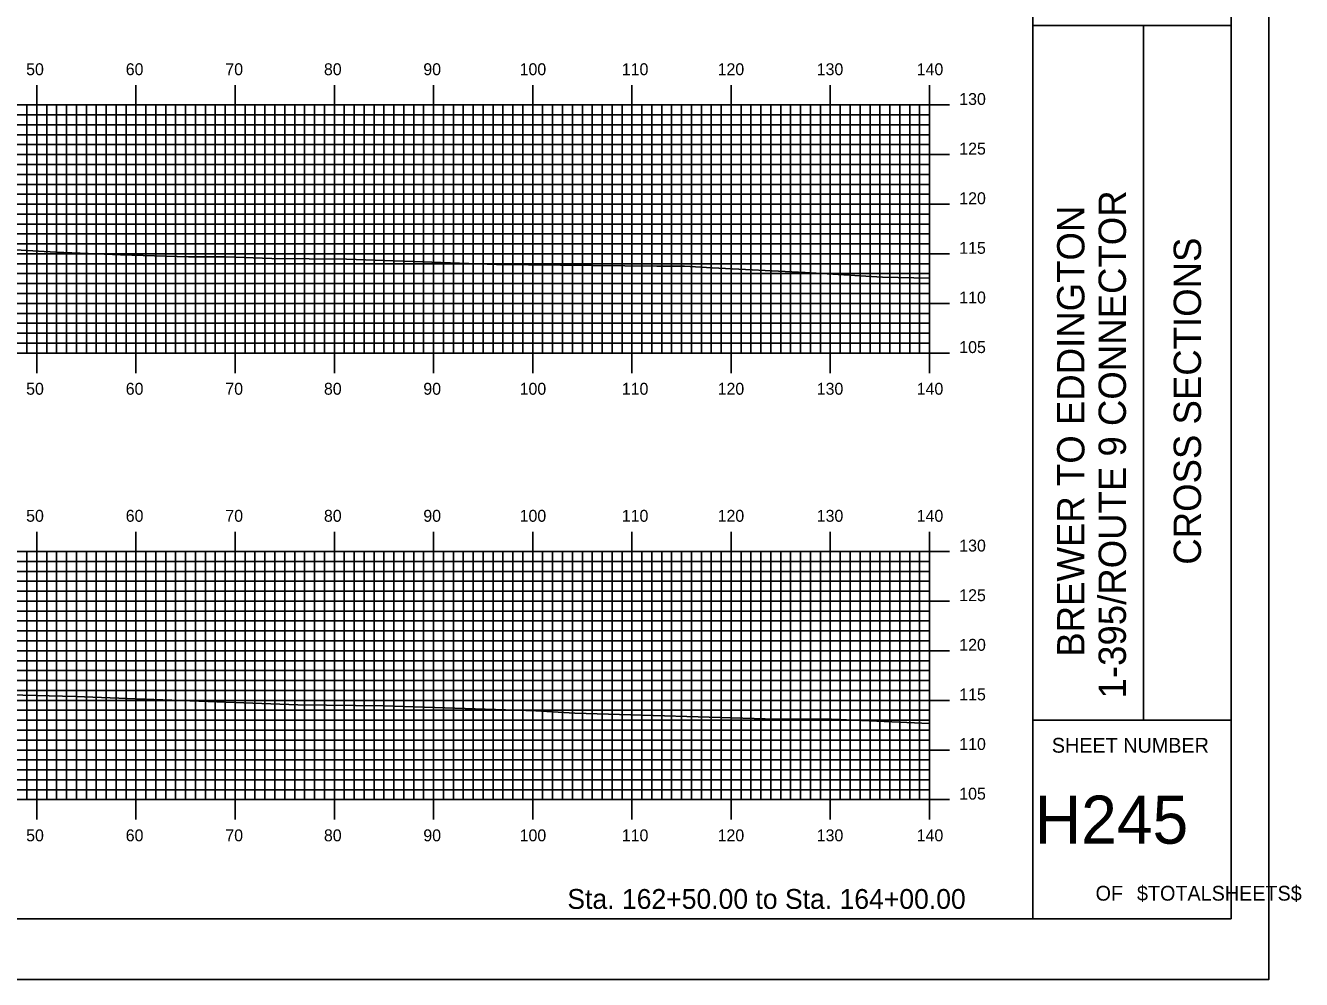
# Model space of a CAD drawing. Extents: x 1780680 to 1781023, y 442591 to 442811.
# Drawn here: x 1780894.2 to 1781022.9, y 442590.5 to 442686.7 of the extents above; entities that cross this region are included whole.
import ezdxf

# ---------------------------------------------------------------- set-up
doc = ezdxf.new("R2010")
doc.units = 0
for name, color, linetype in [('BORDER', 7, 'Continuous'), ('H_V ANNOTATION', 7, 'Continuous'), ('MAJOR', 7, 'Continuous'), ('MINOR', 7, 'Continuous'), ('PLOT BOUNDARY', 7, 'Continuous'), ('S_Roadway_Centerline', 7, 'Continuous')]:
    doc.layers.add(name, color=color, linetype=linetype)

msp = doc.modelspace()

# ---------------------------------------------------------------- linework, layer by layer
at = {"layer": 'BORDER'}
for p, q in [((1780995.78, 442596.67), (1780995.78, 442806.67)), ((1780995.78, 442686.67), (1781015.78, 442686.67)), ((1781006.96, 442616.67), (1781006.96, 442686.67)), ((1780995.78, 442616.67), (1781015.78, 442616.67))]:
    msp.add_line(p, q, dxfattribs=at)
msp.add_lwpolyline([(1780695.78, 442596.67), (1781015.78, 442596.67), (1781015.78, 442806.67), (1780695.78, 442806.67)], close=True, dxfattribs=at)
at = {"layer": 'MAJOR'}
for p, q in [((1780895.38, 442680.67), (1780895.38, 442678.67)), ((1780905.38, 442680.67), (1780905.38, 442678.67)), ((1780915.38, 442680.67), (1780915.38, 442678.67)), ((1780925.38, 442680.67), (1780925.38, 442678.67)), ((1780935.38, 442680.67), (1780935.38, 442678.67)), ((1780945.38, 442680.67), (1780945.38, 442678.67)), ((1780955.38, 442680.67), (1780955.38, 442678.67)), ((1780965.38, 442680.67), (1780965.38, 442678.67)), ((1780975.38, 442680.67), (1780975.38, 442678.67)), ((1780985.38, 442680.67), (1780985.38, 442678.67)), ((1780705.38, 442678.67), (1780985.38, 442678.67)), ((1780705.38, 442678.67), (1780985.38, 442678.67)), ((1780895.38, 442653.67), (1780895.38, 442678.67)), ((1780905.38, 442653.67), (1780905.38, 442678.67)), ((1780915.38, 442653.67), (1780915.38, 442678.67)), ((1780925.38, 442653.67), (1780925.38, 442678.67)), ((1780935.38, 442653.67), (1780935.38, 442678.67)), ((1780945.38, 442653.67), (1780945.38, 442678.67)), ((1780955.38, 442653.67), (1780955.38, 442678.67)), ((1780965.38, 442653.67), (1780965.38, 442678.67)), ((1780975.38, 442653.67), (1780975.38, 442678.67)), ((1780987.39, 442678.67), (1780983.38, 442678.67)), ((1780985.38, 442653.67), (1780985.38, 442678.67)), ((1780985.38, 442653.67), (1780985.38, 442678.67)), ((1780705.38, 442673.67), (1780985.38, 442673.67)), ((1780987.39, 442673.67), (1780983.38, 442673.67)), ((1780705.38, 442668.67), (1780985.38, 442668.67)), ((1780987.39, 442668.67), (1780983.38, 442668.67)), ((1780705.38, 442663.67), (1780985.38, 442663.67)), ((1780987.39, 442663.67), (1780983.38, 442663.67)), ((1780705.38, 442658.67), (1780985.38, 442658.67)), ((1780987.39, 442658.67), (1780983.38, 442658.67)), ((1780705.38, 442653.67), (1780985.38, 442653.67)), ((1780705.38, 442653.67), (1780985.38, 442653.67)), ((1780895.38, 442651.66), (1780895.38, 442653.67)), ((1780905.38, 442651.66), (1780905.38, 442653.67)), ((1780915.38, 442651.66), (1780915.38, 442653.67)), ((1780925.38, 442651.66), (1780925.38, 442653.67)), ((1780935.38, 442651.66), (1780935.38, 442653.67)), ((1780945.38, 442651.66), (1780945.38, 442653.67)), ((1780955.38, 442651.66), (1780955.38, 442653.67)), ((1780965.38, 442651.66), (1780965.38, 442653.67)), ((1780975.38, 442651.66), (1780975.38, 442653.67)), ((1780987.39, 442653.67), (1780983.38, 442653.67)), ((1780985.38, 442651.66), (1780985.38, 442653.67)), ((1780895.38, 442635.67), (1780895.38, 442633.67)), ((1780905.38, 442635.67), (1780905.38, 442633.67)), ((1780915.38, 442635.67), (1780915.38, 442633.67)), ((1780925.38, 442635.67), (1780925.38, 442633.67)), ((1780935.38, 442635.67), (1780935.38, 442633.67)), ((1780945.38, 442635.67), (1780945.38, 442633.67)), ((1780955.38, 442635.67), (1780955.38, 442633.67)), ((1780965.38, 442635.67), (1780965.38, 442633.67)), ((1780975.38, 442635.67), (1780975.38, 442633.67)), ((1780985.38, 442635.67), (1780985.38, 442633.67)), ((1780705.38, 442633.67), (1780985.38, 442633.67)), ((1780705.38, 442633.67), (1780985.38, 442633.67)), ((1780895.38, 442608.67), (1780895.38, 442633.67)), ((1780905.38, 442608.67), (1780905.38, 442633.67)), ((1780915.38, 442608.67), (1780915.38, 442633.67)), ((1780925.38, 442608.67), (1780925.38, 442633.67)), ((1780935.38, 442608.67), (1780935.38, 442633.67)), ((1780945.38, 442608.67), (1780945.38, 442633.67)), ((1780955.38, 442608.67), (1780955.38, 442633.67)), ((1780965.38, 442608.67), (1780965.38, 442633.67)), ((1780975.38, 442608.67), (1780975.38, 442633.67)), ((1780987.39, 442633.67), (1780983.38, 442633.67)), ((1780985.38, 442608.67), (1780985.38, 442633.67)), ((1780985.38, 442608.67), (1780985.38, 442633.67)), ((1780705.38, 442628.67), (1780985.38, 442628.67)), ((1780987.39, 442628.67), (1780983.38, 442628.67)), ((1780705.38, 442623.67), (1780985.38, 442623.67)), ((1780987.39, 442623.67), (1780983.38, 442623.67)), ((1780705.38, 442618.67), (1780985.38, 442618.67)), ((1780987.39, 442618.67), (1780983.38, 442618.67)), ((1780705.38, 442613.67), (1780985.38, 442613.67)), ((1780987.39, 442613.67), (1780983.38, 442613.67)), ((1780705.38, 442608.67), (1780985.38, 442608.67)), ((1780705.38, 442608.67), (1780985.38, 442608.67)), ((1780895.38, 442606.66), (1780895.38, 442608.67)), ((1780905.38, 442606.66), (1780905.38, 442608.67)), ((1780915.38, 442606.66), (1780915.38, 442608.67)), ((1780925.38, 442606.66), (1780925.38, 442608.67)), ((1780935.38, 442606.66), (1780935.38, 442608.67)), ((1780945.38, 442606.66), (1780945.38, 442608.67)), ((1780955.38, 442606.66), (1780955.38, 442608.67)), ((1780965.38, 442606.66), (1780965.38, 442608.67)), ((1780975.38, 442606.66), (1780975.38, 442608.67)), ((1780987.39, 442608.67), (1780983.38, 442608.67)), ((1780985.38, 442606.66), (1780985.38, 442608.67))]:
    msp.add_line(p, q, dxfattribs=at)
at = {"layer": 'MINOR'}
for p, q in [((1780894.38, 442653.67), (1780894.38, 442678.67)), ((1780896.38, 442653.67), (1780896.38, 442678.67)), ((1780897.38, 442653.67), (1780897.38, 442678.67)), ((1780898.38, 442653.67), (1780898.38, 442678.67)), ((1780899.38, 442653.67), (1780899.38, 442678.67)), ((1780900.38, 442653.67), (1780900.38, 442678.67)), ((1780901.38, 442653.67), (1780901.38, 442678.67)), ((1780902.38, 442653.67), (1780902.38, 442678.67)), ((1780903.38, 442653.67), (1780903.38, 442678.67)), ((1780904.38, 442653.67), (1780904.38, 442678.67)), ((1780906.38, 442653.67), (1780906.38, 442678.67)), ((1780907.38, 442653.67), (1780907.38, 442678.67)), ((1780908.38, 442653.67), (1780908.38, 442678.67)), ((1780909.38, 442653.67), (1780909.38, 442678.67)), ((1780910.38, 442653.67), (1780910.38, 442678.67)), ((1780911.38, 442653.67), (1780911.38, 442678.67)), ((1780912.38, 442653.67), (1780912.38, 442678.67)), ((1780913.38, 442653.67), (1780913.38, 442678.67)), ((1780914.38, 442653.67), (1780914.38, 442678.67)), ((1780916.38, 442653.67), (1780916.38, 442678.67)), ((1780917.38, 442653.67), (1780917.38, 442678.67)), ((1780918.38, 442653.67), (1780918.38, 442678.67)), ((1780919.38, 442653.67), (1780919.38, 442678.67)), ((1780920.38, 442653.67), (1780920.38, 442678.67)), ((1780921.38, 442653.67), (1780921.38, 442678.67)), ((1780922.38, 442653.67), (1780922.38, 442678.67)), ((1780923.38, 442653.67), (1780923.38, 442678.67)), ((1780924.38, 442653.67), (1780924.38, 442678.67)), ((1780926.38, 442653.67), (1780926.38, 442678.67)), ((1780927.38, 442653.67), (1780927.38, 442678.67)), ((1780928.38, 442653.67), (1780928.38, 442678.67)), ((1780929.38, 442653.67), (1780929.38, 442678.67)), ((1780930.38, 442653.67), (1780930.38, 442678.67)), ((1780931.38, 442653.67), (1780931.38, 442678.67)), ((1780932.38, 442653.67), (1780932.38, 442678.67)), ((1780933.38, 442653.67), (1780933.38, 442678.67)), ((1780934.38, 442653.67), (1780934.38, 442678.67)), ((1780936.38, 442653.67), (1780936.38, 442678.67)), ((1780937.38, 442653.67), (1780937.38, 442678.67)), ((1780938.38, 442653.67), (1780938.38, 442678.67)), ((1780939.38, 442653.67), (1780939.38, 442678.67)), ((1780940.38, 442653.67), (1780940.38, 442678.67)), ((1780941.38, 442653.67), (1780941.38, 442678.67)), ((1780942.38, 442653.67), (1780942.38, 442678.67)), ((1780943.38, 442653.67), (1780943.38, 442678.67)), ((1780944.38, 442653.67), (1780944.38, 442678.67)), ((1780946.38, 442653.67), (1780946.38, 442678.67)), ((1780947.38, 442653.67), (1780947.38, 442678.67)), ((1780948.38, 442653.67), (1780948.38, 442678.67)), ((1780949.38, 442653.67), (1780949.38, 442678.67)), ((1780950.38, 442653.67), (1780950.38, 442678.67)), ((1780951.38, 442653.67), (1780951.38, 442678.67)), ((1780952.38, 442653.67), (1780952.38, 442678.67)), ((1780953.38, 442653.67), (1780953.38, 442678.67)), ((1780954.38, 442653.67), (1780954.38, 442678.67)), ((1780956.38, 442653.67), (1780956.38, 442678.67)), ((1780957.38, 442653.67), (1780957.38, 442678.67)), ((1780958.38, 442653.67), (1780958.38, 442678.67)), ((1780959.38, 442653.67), (1780959.38, 442678.67)), ((1780960.38, 442653.67), (1780960.38, 442678.67)), ((1780961.38, 442653.67), (1780961.38, 442678.67)), ((1780962.38, 442653.67), (1780962.38, 442678.67)), ((1780963.38, 442653.67), (1780963.38, 442678.67)), ((1780964.38, 442653.67), (1780964.38, 442678.67)), ((1780966.38, 442653.67), (1780966.38, 442678.67)), ((1780967.38, 442653.67), (1780967.38, 442678.67)), ((1780968.38, 442653.67), (1780968.38, 442678.67)), ((1780969.38, 442653.67), (1780969.38, 442678.67)), ((1780970.38, 442653.67), (1780970.38, 442678.67)), ((1780971.38, 442653.67), (1780971.38, 442678.67)), ((1780972.38, 442653.67), (1780972.38, 442678.67)), ((1780973.38, 442653.67), (1780973.38, 442678.67)), ((1780974.38, 442653.67), (1780974.38, 442678.67)), ((1780976.38, 442653.67), (1780976.38, 442678.67)), ((1780977.38, 442653.67), (1780977.38, 442678.67)), ((1780978.38, 442653.67), (1780978.38, 442678.67)), ((1780979.38, 442653.67), (1780979.38, 442678.67)), ((1780980.38, 442653.67), (1780980.38, 442678.67)), ((1780981.38, 442653.67), (1780981.38, 442678.67)), ((1780982.38, 442653.67), (1780982.38, 442678.67)), ((1780983.38, 442653.67), (1780983.38, 442678.67)), ((1780984.38, 442653.67), (1780984.38, 442678.67)), ((1780705.38, 442677.67), (1780985.38, 442677.67)), ((1780985.38, 442677.67), (1780983.38, 442677.67)), ((1780705.38, 442676.67), (1780985.38, 442676.67)), ((1780705.38, 442675.67), (1780985.38, 442675.67)), ((1780985.38, 442676.67), (1780983.38, 442676.67)), ((1780985.38, 442675.67), (1780983.38, 442675.67)), ((1780705.38, 442674.67), (1780985.38, 442674.67)), ((1780985.38, 442674.67), (1780983.38, 442674.67)), ((1780705.38, 442672.67), (1780985.38, 442672.67)), ((1780705.38, 442671.67), (1780985.38, 442671.67)), ((1780985.38, 442672.67), (1780983.38, 442672.67)), ((1780985.38, 442671.67), (1780983.38, 442671.67)), ((1780705.38, 442670.67), (1780985.38, 442670.67)), ((1780985.38, 442670.67), (1780983.38, 442670.67)), ((1780705.38, 442669.67), (1780985.38, 442669.67)), ((1780985.38, 442669.67), (1780983.38, 442669.67)), ((1780705.38, 442667.67), (1780985.38, 442667.67)), ((1780705.38, 442666.67), (1780985.38, 442666.67)), ((1780985.38, 442667.67), (1780983.38, 442667.67)), ((1780985.38, 442666.67), (1780983.38, 442666.67)), ((1780705.38, 442665.67), (1780985.38, 442665.67)), ((1780985.38, 442665.67), (1780983.38, 442665.67)), ((1780705.38, 442664.67), (1780985.38, 442664.67)), ((1780985.38, 442664.67), (1780983.38, 442664.67)), ((1780705.38, 442662.67), (1780985.38, 442662.67)), ((1780985.38, 442662.67), (1780983.38, 442662.67)), ((1780705.38, 442661.67), (1780985.38, 442661.67)), ((1780985.38, 442661.67), (1780983.38, 442661.67)), ((1780705.38, 442660.67), (1780985.38, 442660.67)), ((1780985.38, 442660.67), (1780983.38, 442660.67)), ((1780705.38, 442659.67), (1780985.38, 442659.67)), ((1780985.38, 442659.67), (1780983.38, 442659.67)), ((1780705.38, 442657.67), (1780985.38, 442657.67)), ((1780985.38, 442657.67), (1780983.38, 442657.67)), ((1780705.38, 442656.67), (1780985.38, 442656.67)), ((1780985.38, 442656.67), (1780983.38, 442656.67)), ((1780705.38, 442655.67), (1780985.38, 442655.67)), ((1780985.38, 442655.67), (1780983.38, 442655.67)), ((1780705.38, 442654.67), (1780985.38, 442654.67)), ((1780985.38, 442654.67), (1780983.38, 442654.67)), ((1780894.38, 442608.67), (1780894.38, 442633.67)), ((1780896.38, 442608.67), (1780896.38, 442633.67)), ((1780897.38, 442608.67), (1780897.38, 442633.67)), ((1780898.38, 442608.67), (1780898.38, 442633.67)), ((1780899.38, 442608.67), (1780899.38, 442633.67)), ((1780900.38, 442608.67), (1780900.38, 442633.67)), ((1780901.38, 442608.67), (1780901.38, 442633.67)), ((1780902.38, 442608.67), (1780902.38, 442633.67)), ((1780903.38, 442608.67), (1780903.38, 442633.67)), ((1780904.38, 442608.67), (1780904.38, 442633.67)), ((1780906.38, 442608.67), (1780906.38, 442633.67)), ((1780907.38, 442608.67), (1780907.38, 442633.67)), ((1780908.38, 442608.67), (1780908.38, 442633.67)), ((1780909.38, 442608.67), (1780909.38, 442633.67)), ((1780910.38, 442608.67), (1780910.38, 442633.67)), ((1780911.38, 442608.67), (1780911.38, 442633.67)), ((1780912.38, 442608.67), (1780912.38, 442633.67)), ((1780913.38, 442608.67), (1780913.38, 442633.67)), ((1780914.38, 442608.67), (1780914.38, 442633.67)), ((1780916.38, 442608.67), (1780916.38, 442633.67)), ((1780917.38, 442608.67), (1780917.38, 442633.67)), ((1780918.38, 442608.67), (1780918.38, 442633.67)), ((1780919.38, 442608.67), (1780919.38, 442633.67)), ((1780920.38, 442608.67), (1780920.38, 442633.67)), ((1780921.38, 442608.67), (1780921.38, 442633.67)), ((1780922.38, 442608.67), (1780922.38, 442633.67)), ((1780923.38, 442608.67), (1780923.38, 442633.67)), ((1780924.38, 442608.67), (1780924.38, 442633.67)), ((1780926.38, 442608.67), (1780926.38, 442633.67)), ((1780927.38, 442608.67), (1780927.38, 442633.67)), ((1780928.38, 442608.67), (1780928.38, 442633.67)), ((1780929.38, 442608.67), (1780929.38, 442633.67)), ((1780930.38, 442608.67), (1780930.38, 442633.67)), ((1780931.38, 442608.67), (1780931.38, 442633.67)), ((1780932.38, 442608.67), (1780932.38, 442633.67)), ((1780933.38, 442608.67), (1780933.38, 442633.67)), ((1780934.38, 442608.67), (1780934.38, 442633.67)), ((1780936.38, 442608.67), (1780936.38, 442633.67)), ((1780937.38, 442608.67), (1780937.38, 442633.67)), ((1780938.38, 442608.67), (1780938.38, 442633.67)), ((1780939.38, 442608.67), (1780939.38, 442633.67)), ((1780940.38, 442608.67), (1780940.38, 442633.67)), ((1780941.38, 442608.67), (1780941.38, 442633.67)), ((1780942.38, 442608.67), (1780942.38, 442633.67)), ((1780943.38, 442608.67), (1780943.38, 442633.67)), ((1780944.38, 442608.67), (1780944.38, 442633.67)), ((1780946.38, 442608.67), (1780946.38, 442633.67)), ((1780947.38, 442608.67), (1780947.38, 442633.67)), ((1780948.38, 442608.67), (1780948.38, 442633.67)), ((1780949.38, 442608.67), (1780949.38, 442633.67)), ((1780950.38, 442608.67), (1780950.38, 442633.67)), ((1780951.38, 442608.67), (1780951.38, 442633.67)), ((1780952.38, 442608.67), (1780952.38, 442633.67)), ((1780953.38, 442608.67), (1780953.38, 442633.67)), ((1780954.38, 442608.67), (1780954.38, 442633.67)), ((1780956.38, 442608.67), (1780956.38, 442633.67)), ((1780957.38, 442608.67), (1780957.38, 442633.67)), ((1780958.38, 442608.67), (1780958.38, 442633.67)), ((1780959.38, 442608.67), (1780959.38, 442633.67)), ((1780960.38, 442608.67), (1780960.38, 442633.67)), ((1780961.38, 442608.67), (1780961.38, 442633.67)), ((1780962.38, 442608.67), (1780962.38, 442633.67)), ((1780963.38, 442608.67), (1780963.38, 442633.67)), ((1780964.38, 442608.67), (1780964.38, 442633.67)), ((1780966.38, 442608.67), (1780966.38, 442633.67)), ((1780967.38, 442608.67), (1780967.38, 442633.67)), ((1780968.38, 442608.67), (1780968.38, 442633.67)), ((1780969.38, 442608.67), (1780969.38, 442633.67)), ((1780970.38, 442608.67), (1780970.38, 442633.67)), ((1780971.38, 442608.67), (1780971.38, 442633.67)), ((1780972.38, 442608.67), (1780972.38, 442633.67)), ((1780973.38, 442608.67), (1780973.38, 442633.67)), ((1780974.38, 442608.67), (1780974.38, 442633.67)), ((1780976.38, 442608.67), (1780976.38, 442633.67)), ((1780977.38, 442608.67), (1780977.38, 442633.67)), ((1780978.38, 442608.67), (1780978.38, 442633.67)), ((1780979.38, 442608.67), (1780979.38, 442633.67)), ((1780980.38, 442608.67), (1780980.38, 442633.67)), ((1780981.38, 442608.67), (1780981.38, 442633.67)), ((1780982.38, 442608.67), (1780982.38, 442633.67)), ((1780983.38, 442608.67), (1780983.38, 442633.67)), ((1780984.38, 442608.67), (1780984.38, 442633.67)), ((1780705.38, 442632.67), (1780985.38, 442632.67)), ((1780985.38, 442632.67), (1780983.38, 442632.67)), ((1780705.38, 442631.67), (1780985.38, 442631.67)), ((1780705.38, 442630.67), (1780985.38, 442630.67)), ((1780985.38, 442631.67), (1780983.38, 442631.67)), ((1780985.38, 442630.67), (1780983.38, 442630.67)), ((1780705.38, 442629.67), (1780985.38, 442629.67)), ((1780985.38, 442629.67), (1780983.38, 442629.67)), ((1780705.38, 442627.67), (1780985.38, 442627.67)), ((1780705.38, 442626.67), (1780985.38, 442626.67)), ((1780985.38, 442627.67), (1780983.38, 442627.67)), ((1780985.38, 442626.67), (1780983.38, 442626.67)), ((1780705.38, 442625.67), (1780985.38, 442625.67)), ((1780985.38, 442625.67), (1780983.38, 442625.67)), ((1780705.38, 442624.67), (1780985.38, 442624.67)), ((1780985.38, 442624.67), (1780983.38, 442624.67)), ((1780705.38, 442622.67), (1780985.38, 442622.67)), ((1780705.38, 442621.67), (1780985.38, 442621.67)), ((1780985.38, 442622.67), (1780983.38, 442622.67)), ((1780985.38, 442621.67), (1780983.38, 442621.67)), ((1780705.38, 442620.67), (1780985.38, 442620.67)), ((1780985.38, 442620.67), (1780983.38, 442620.67)), ((1780705.38, 442619.67), (1780985.38, 442619.67)), ((1780985.38, 442619.67), (1780983.38, 442619.67)), ((1780705.38, 442617.67), (1780985.38, 442617.67)), ((1780985.38, 442617.67), (1780983.38, 442617.67)), ((1780705.38, 442616.67), (1780985.38, 442616.67)), ((1780985.38, 442616.67), (1780983.38, 442616.67)), ((1780705.38, 442615.67), (1780985.38, 442615.67)), ((1780985.38, 442615.67), (1780983.38, 442615.67)), ((1780705.38, 442614.67), (1780985.38, 442614.67)), ((1780985.38, 442614.67), (1780983.38, 442614.67)), ((1780705.38, 442612.67), (1780985.38, 442612.67)), ((1780985.38, 442612.67), (1780983.38, 442612.67)), ((1780705.38, 442611.67), (1780985.38, 442611.67)), ((1780985.38, 442611.67), (1780983.38, 442611.67)), ((1780705.38, 442610.67), (1780985.38, 442610.67)), ((1780985.38, 442610.67), (1780983.38, 442610.67)), ((1780705.38, 442609.67), (1780985.38, 442609.67)), ((1780985.38, 442609.67), (1780983.38, 442609.67))]:
    msp.add_line(p, q, dxfattribs=at)
at = {"layer": 'PLOT BOUNDARY'}
msp.add_lwpolyline([(1780679.59, 442590.55), (1781019.59, 442590.55), (1781019.59, 442810.55), (1780679.59, 442810.55)], close=True, dxfattribs=at)
at = {"layer": 'S_Roadway_Centerline'}
for points in [[(1780891.46, 442664.18), (1780897.29, 442663.85), (1780903.83, 442663.58), (1780910.66, 442663.36), (1780914.41, 442663.38), (1780919.07, 442663.21), (1780926.61, 442663.12), (1780933.36, 442662.9), (1780941.71, 442662.58), (1780957.88, 442662.41), (1780960.69, 442662.42), (1780963.47, 442662.27), (1780972.83, 442661.8), (1780980.63, 442661.32), (1780985.38, 442661.22)], [(1780891.24, 442619.25), (1780899.31, 442619.06), (1780905.36, 442618.84), (1780921.69, 442618.22), (1780930.41, 442618.12), (1780945.68, 442617.63), (1780949.61, 442617.38), (1780969.95, 442616.78), (1780975.49, 442616.77), (1780985.38, 442616.34)]]:
    msp.add_lwpolyline(points, dxfattribs=at)

# ---------------------------------------------------------------- texts
at = {"layer": 'BORDER'}
for s, p in [('1-395/ROUTE 9 CONNECTOR', (1781005.18, 442618.87)), ('BREWER TO EDDINGTON', (1781001, 442623.07)), ('CROSS SECTIONS', (1781012.75, 442632.34))]:
    msp.add_text(s, height=2.7557, rotation=90, dxfattribs=at).set_placement(p)
for s, height, p in [('SHEET NUMBER', 1.4905, (1780997.71, 442613.4)), ('H245', 4.839, (1780995.99, 442604.23)), ('OF', 1.491, (1781002.12, 442598.49)), ('$TOTALSHEETS$', 1.4905, (1781006.29, 442598.49))]:
    msp.add_text(s, height=height, dxfattribs=at).set_placement(p)
at = {"layer": 'H_V ANNOTATION'}
for s, height, p in [('50', 1.2, (1780894.31, 442681.67)), ('60', 1.2, (1780904.35, 442681.67)), ('70', 1.2, (1780914.39, 442681.67)), ('80', 1.2, (1780924.33, 442681.67)), ('90', 1.2, (1780934.35, 442681.67)), ('100', 1.2, (1780944.06, 442681.67)), ('110', 1.2, (1780954.36, 442681.67)), ('120', 1.2, (1780964.02, 442681.67)), ('130', 1.2, (1780974.01, 442681.67)), ('140', 1.2, (1780984.09, 442681.67)), ('130', 1.2, (1780988.38, 442678.67)), ('125', 1.2, (1780988.38, 442673.67)), ('120', 1.2, (1780988.38, 442668.67)), ('115', 1.2, (1780988.38, 442663.67)), ('110', 1.2, (1780988.38, 442658.67)), ('105', 1.2, (1780988.38, 442653.67)), ('50', 1.2, (1780894.31, 442649.47)), ('60', 1.2, (1780904.35, 442649.47)), ('70', 1.2, (1780914.39, 442649.47)), ('80', 1.2, (1780924.33, 442649.47)), ('90', 1.2, (1780934.35, 442649.47)), ('100', 1.2, (1780944.06, 442649.47)), ('110', 1.2, (1780954.36, 442649.47)), ('120', 1.2, (1780964.02, 442649.47)), ('130', 1.2, (1780974.01, 442649.47)), ('140', 1.2, (1780984.09, 442649.47)), ('50', 1.2, (1780894.31, 442636.67)), ('60', 1.2, (1780904.35, 442636.67)), ('70', 1.2, (1780914.39, 442636.67)), ('80', 1.2, (1780924.33, 442636.67)), ('90', 1.2, (1780934.35, 442636.67)), ('100', 1.2, (1780944.06, 442636.67)), ('110', 1.2, (1780954.36, 442636.67)), ('120', 1.2, (1780964.02, 442636.67)), ('130', 1.2, (1780974.01, 442636.67)), ('140', 1.2, (1780984.09, 442636.67)), ('130', 1.2, (1780988.38, 442633.67)), ('125', 1.2, (1780988.38, 442628.67)), ('120', 1.2, (1780988.38, 442623.67)), ('115', 1.2, (1780988.38, 442618.67)), ('110', 1.2, (1780988.38, 442613.67)), ('105', 1.2, (1780988.38, 442608.67)), ('50', 1.2, (1780894.31, 442604.47)), ('60', 1.2, (1780904.35, 442604.47)), ('70', 1.2, (1780914.39, 442604.47)), ('80', 1.2, (1780924.33, 442604.47)), ('90', 1.2, (1780934.35, 442604.47)), ('100', 1.2, (1780944.06, 442604.47)), ('110', 1.2, (1780954.36, 442604.47)), ('120', 1.2, (1780964.02, 442604.47)), ('130', 1.2, (1780974.01, 442604.47)), ('140', 1.2, (1780984.09, 442604.47)), ('Sta. 162+50.00 to Sta. 164+00.00', 2.0004, (1780948.87, 442597.66))]:
    msp.add_text(s, height=height, dxfattribs=at).set_placement(p)

doc.saveas('drawing.dxf')
